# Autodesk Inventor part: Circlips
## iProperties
Shininess: 20.0
Angle Display Precision: 2
Document Length Units: 11269
Document Angle Units: 11279
Document Time Units: 11290
Document Mass Units: 11283
Document Length Units Precision: 3
Document Angle Units Precision: 2
Created: 2002-09
Part Number: Circlips
Material: Par défaut
Document SubType Name: Modélisation
Designer: administrateur
Density: 0.0
Volumn: 0.0
Area: 0.0
PropertySet Name: Model Information
Control State: 0
Master: False
Checked Out: False
Author: administrateur
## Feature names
1. Extrusion1
2. Symétrie2 [Mirror]
